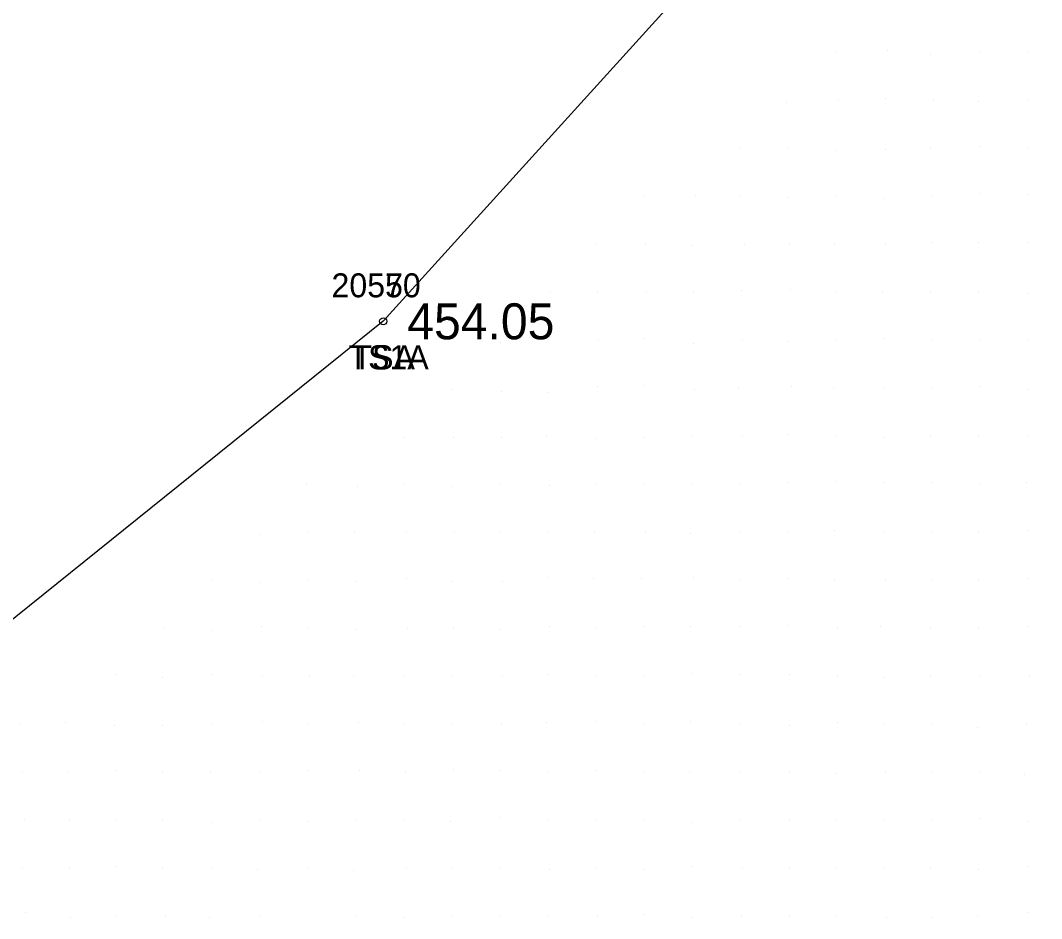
# Model space of a CAD drawing. Extents: x 1747760 to 1751131, y 649333 to 653784.
# Drawn here: x 1749057.32 to 1749099.9, y 651438.67 to 651476.11 of the extents above; entities that cross this region are included whole.
import ezdxf

# ---------------------------------------------------------------- set-up
doc = ezdxf.new("R2010")
doc.units = 0
for name, color, linetype in [('RD_DTM_BkLn2', 7, 'Continuous'), ('RD_DTM_BkLn_txCode', 7, 'Continuous'), ('RD_DTM_Spot', 7, 'Continuous'), ('RD_EX_TX_Misc_ELEV', 7, 'Continuous'), ('RD_SMD_Locator', 7, 'Continuous')]:
    doc.layers.add(name, color=color, linetype=linetype)

msp = doc.modelspace()

# ---------------------------------------------------------------- linework, layer by layer
at = {"layer": 'RD_DTM_BkLn2'}
for points in [[(1749072.449, 651463.568), (1749102.17, 651496.369), (1749126.542, 651516.467), (1749148.35, 651529.918), (1749165.728, 651545.441)], [(1749072.449, 651463.568), (1749050.274, 651445.743), (1749030.789, 651430.079), (1749011.304, 651414.416)]]:
    msp.add_lwpolyline(points, dxfattribs=at)
at = {"layer": 'RD_DTM_Spot'}
for p, q in [((1749091.356, 651474.816), (1749091.356, 651474.816)), ((1749093.471, 651474.844), (1749093.471, 651474.844)), ((1749095.285, 651474.697), (1749095.285, 651474.697)), ((1749097.31, 651474.81), (1749097.31, 651474.81)), ((1749099.306, 651474.798), (1749099.306, 651474.798)), ((1749089.246, 651472.694), (1749089.246, 651472.694)), ((1749091.422, 651472.754), (1749091.422, 651472.754)), ((1749093.385, 651472.838), (1749093.385, 651472.838)), ((1749095.394, 651472.826), (1749095.394, 651472.826)), ((1749097.271, 651472.74), (1749097.271, 651472.74)), ((1749099.296, 651472.808), (1749099.296, 651472.808)), ((1749097.327, 651470.844), (1749097.327, 651470.844)), ((1749087.317, 651470.817), (1749087.317, 651470.817)), ((1749089.328, 651470.774), (1749089.328, 651470.774)), ((1749091.316, 651470.685), (1749091.316, 651470.685)), ((1749093.381, 651470.748), (1749093.381, 651470.748)), ((1749095.272, 651470.792), (1749095.272, 651470.792)), ((1749099.348, 651470.815), (1749099.348, 651470.815)), ((1749083.356, 651468.808), (1749083.356, 651468.808)), ((1749085.457, 651468.82), (1749085.457, 651468.82)), ((1749087.33, 651468.754), (1749087.33, 651468.754)), ((1749089.32, 651468.748), (1749089.32, 651468.748)), ((1749091.358, 651468.767), (1749091.358, 651468.767)), ((1749095.31, 651468.759), (1749095.31, 651468.759)), ((1749097.314, 651468.878), (1749097.314, 651468.878)), ((1749099.353, 651468.846), (1749099.353, 651468.846)), ((1749093.359, 651468.703), (1749093.359, 651468.703)), ((1749081.338, 651466.831), (1749081.338, 651466.831)), ((1749083.403, 651466.767), (1749083.403, 651466.767)), ((1749085.323, 651466.734), (1749085.323, 651466.734)), ((1749087.501, 651466.763), (1749087.501, 651466.763)), ((1749089.398, 651466.778), (1749089.398, 651466.778)), ((1749091.256, 651466.805), (1749091.256, 651466.805)), ((1749093.377, 651466.807), (1749093.377, 651466.807)), ((1749095.361, 651466.859), (1749095.361, 651466.859)), ((1749097.257, 651466.842), (1749097.257, 651466.842)), ((1749099.345, 651466.844), (1749099.345, 651466.844)), ((1749079.435, 651464.773), (1749079.435, 651464.773)), ((1749081.385, 651464.777), (1749081.385, 651464.777)), ((1749083.433, 651464.761), (1749083.433, 651464.761)), ((1749085.365, 651464.802), (1749085.365, 651464.802)), ((1749087.372, 651464.852), (1749087.372, 651464.852)), ((1749089.446, 651464.88), (1749089.446, 651464.88)), ((1749091.318, 651464.767), (1749091.318, 651464.767)), ((1749093.281, 651464.792), (1749093.281, 651464.792)), ((1749095.259, 651464.798), (1749095.259, 651464.798)), ((1749097.251, 651464.757), (1749097.251, 651464.757)), ((1749099.347, 651464.709), (1749099.347, 651464.709)), ((1749079.27, 651462.837), (1749079.27, 651462.837)), ((1749081.415, 651462.772), (1749081.415, 651462.772)), ((1749083.291, 651462.84), (1749083.291, 651462.84)), ((1749087.445, 651462.788), (1749087.445, 651462.788)), ((1749091.333, 651462.823), (1749091.333, 651462.823)), ((1749093.363, 651462.859), (1749093.363, 651462.859)), ((1749095.299, 651462.799), (1749095.299, 651462.799)), ((1749097.317, 651462.802), (1749097.317, 651462.802)), ((1749099.299, 651462.785), (1749099.299, 651462.785)), ((1749077.337, 651462.686), (1749077.337, 651462.686)), ((1749085.378, 651462.662), (1749085.378, 651462.662)), ((1749089.307, 651462.731), (1749089.307, 651462.731)), ((1749075.355, 651460.723), (1749075.355, 651460.723)), ((1749077.396, 651460.657), (1749077.396, 651460.657)), ((1749081.373, 651460.838), (1749081.373, 651460.838)), ((1749083.29, 651460.88), (1749083.29, 651460.88)), ((1749085.439, 651460.746), (1749085.439, 651460.746)), ((1749087.272, 651460.75), (1749087.272, 651460.75)), ((1749089.455, 651460.86), (1749089.455, 651460.86)), ((1749091.241, 651460.767), (1749091.241, 651460.767)), ((1749093.346, 651460.755), (1749093.346, 651460.755)), ((1749095.288, 651460.794), (1749095.288, 651460.794)), ((1749097.317, 651460.864), (1749097.317, 651460.864)), ((1749099.349, 651460.717), (1749099.349, 651460.717)), ((1749079.353, 651460.612), (1749079.353, 651460.612)), ((1749073.348, 651458.718), (1749073.348, 651458.718)), ((1749075.378, 651458.74), (1749075.378, 651458.74)), ((1749077.377, 651458.738), (1749077.377, 651458.738)), ((1749079.268, 651458.756), (1749079.268, 651458.756)), ((1749081.335, 651458.699), (1749081.335, 651458.699)), ((1749083.282, 651458.726), (1749083.282, 651458.726)), ((1749085.337, 651458.759), (1749085.337, 651458.759)), ((1749087.424, 651458.805), (1749087.424, 651458.805)), ((1749089.334, 651458.859), (1749089.334, 651458.859)), ((1749091.336, 651458.758), (1749091.336, 651458.758)), ((1749093.336, 651458.73), (1749093.336, 651458.73)), ((1749095.285, 651458.819), (1749095.285, 651458.819)), ((1749097.25, 651458.772), (1749097.25, 651458.772)), ((1749099.306, 651458.758), (1749099.306, 651458.758)), ((1749073.345, 651456.796), (1749073.345, 651456.796)), ((1749085.315, 651456.825), (1749085.315, 651456.825)), ((1749089.297, 651456.849), (1749089.297, 651456.849)), ((1749091.357, 651456.904), (1749091.357, 651456.904)), ((1749093.3, 651456.851), (1749093.3, 651456.851)), ((1749095.347, 651456.837), (1749095.347, 651456.837)), ((1749099.258, 651456.844), (1749099.258, 651456.844)), ((1749069.263, 651456.787), (1749069.263, 651456.787)), ((1749071.364, 651456.694), (1749071.364, 651456.694)), ((1749075.301, 651456.684), (1749075.301, 651456.684)), ((1749077.356, 651456.761), (1749077.356, 651456.761)), ((1749079.38, 651456.734), (1749079.38, 651456.734)), ((1749081.293, 651456.767), (1749081.293, 651456.767)), ((1749083.281, 651456.77), (1749083.281, 651456.77)), ((1749087.359, 651456.756), (1749087.359, 651456.756)), ((1749097.297, 651456.758), (1749097.297, 651456.758)), ((1749067.311, 651454.686), (1749067.311, 651454.686)), ((1749069.33, 651454.773), (1749069.33, 651454.773)), ((1749071.245, 651454.796), (1749071.245, 651454.796)), ((1749073.42, 651454.758), (1749073.42, 651454.758)), ((1749075.406, 651454.805), (1749075.406, 651454.805)), ((1749077.322, 651454.751), (1749077.322, 651454.751)), ((1749079.339, 651454.775), (1749079.339, 651454.775)), ((1749081.277, 651454.789), (1749081.277, 651454.789)), ((1749083.366, 651454.818), (1749083.366, 651454.818)), ((1749085.265, 651454.72), (1749085.265, 651454.72)), ((1749087.32, 651454.749), (1749087.32, 651454.749)), ((1749089.358, 651454.783), (1749089.358, 651454.783)), ((1749091.247, 651454.841), (1749091.247, 651454.841)), ((1749093.338, 651454.824), (1749093.338, 651454.824)), ((1749095.365, 651454.823), (1749095.365, 651454.823)), ((1749097.286, 651454.811), (1749097.286, 651454.811)), ((1749099.296, 651454.834), (1749099.296, 651454.834)), ((1749065.304, 651452.79), (1749065.304, 651452.79)), ((1749067.345, 651452.697), (1749067.345, 651452.697)), ((1749069.271, 651452.745), (1749069.271, 651452.745)), ((1749071.345, 651452.714), (1749071.345, 651452.714)), ((1749073.411, 651452.847), (1749073.411, 651452.847)), ((1749075.322, 651452.703), (1749075.322, 651452.703)), ((1749077.406, 651452.73), (1749077.406, 651452.73)), ((1749079.326, 651452.874), (1749079.326, 651452.874)), ((1749081.228, 651452.837), (1749081.228, 651452.837)), ((1749083.204, 651452.864), (1749083.204, 651452.864)), ((1749085.379, 651452.905), (1749085.379, 651452.905)), ((1749087.317, 651452.806), (1749087.317, 651452.806)), ((1749089.342, 651452.832), (1749089.342, 651452.832)), ((1749091.273, 651452.783), (1749091.273, 651452.783)), ((1749093.373, 651452.78), (1749093.373, 651452.78)), ((1749095.308, 651452.779), (1749095.308, 651452.779)), ((1749097.272, 651452.775), (1749097.272, 651452.775)), ((1749099.332, 651452.825), (1749099.332, 651452.825)), ((1749079.378, 651450.854), (1749079.378, 651450.854)), ((1749083.307, 651450.836), (1749083.307, 651450.836)), ((1749085.272, 651450.837), (1749085.272, 651450.837)), ((1749087.285, 651450.86), (1749087.285, 651450.86)), ((1749089.361, 651450.866), (1749089.361, 651450.866)), ((1749093.186, 651450.834), (1749093.186, 651450.834)), ((1749099.355, 651450.859), (1749099.355, 651450.859)), ((1749063.333, 651450.81), (1749063.333, 651450.81)), ((1749065.317, 651450.688), (1749065.317, 651450.688)), ((1749067.371, 651450.825), (1749067.371, 651450.825)), ((1749069.274, 651450.768), (1749069.274, 651450.768)), ((1749071.321, 651450.715), (1749071.321, 651450.715)), ((1749073.467, 651450.78), (1749073.467, 651450.78)), ((1749075.388, 651450.795), (1749075.388, 651450.795)), ((1749077.333, 651450.729), (1749077.333, 651450.729)), ((1749081.302, 651450.769), (1749081.302, 651450.769)), ((1749091.369, 651450.802), (1749091.369, 651450.802)), ((1749095.259, 651450.777), (1749095.259, 651450.777)), ((1749097.263, 651450.802), (1749097.263, 651450.802)), ((1749061.271, 651448.828), (1749061.271, 651448.828)), ((1749063.229, 651448.731), (1749063.229, 651448.731)), ((1749065.35, 651448.847), (1749065.35, 651448.847)), ((1749067.394, 651448.755), (1749067.394, 651448.755)), ((1749069.366, 651448.804), (1749069.366, 651448.804)), ((1749071.216, 651448.776), (1749071.216, 651448.776)), ((1749073.276, 651448.782), (1749073.276, 651448.782)), ((1749075.32, 651448.814), (1749075.32, 651448.814)), ((1749077.404, 651448.813), (1749077.404, 651448.813)), ((1749079.305, 651448.84), (1749079.305, 651448.84)), ((1749081.312, 651448.812), (1749081.312, 651448.812)), ((1749083.318, 651448.785), (1749083.318, 651448.785)), ((1749085.291, 651448.872), (1749085.291, 651448.872)), ((1749087.322, 651448.844), (1749087.322, 651448.844)), ((1749089.396, 651448.852), (1749089.396, 651448.852)), ((1749091.379, 651448.801), (1749091.379, 651448.801)), ((1749093.362, 651448.712), (1749093.362, 651448.712)), ((1749095.254, 651448.791), (1749095.254, 651448.791)), ((1749097.331, 651448.786), (1749097.331, 651448.786)), ((1749099.391, 651448.757), (1749099.391, 651448.757)), ((1749057.33, 651446.811), (1749057.33, 651446.811)), ((1749059.204, 651446.835), (1749059.204, 651446.835)), ((1749061.233, 651446.723), (1749061.233, 651446.723)), ((1749063.233, 651446.71), (1749063.233, 651446.71)), ((1749065.294, 651446.744), (1749065.294, 651446.744)), ((1749067.401, 651446.865), (1749067.401, 651446.865)), ((1749069.315, 651446.771), (1749069.315, 651446.771)), ((1749071.423, 651446.829), (1749071.423, 651446.829)), ((1749073.303, 651446.813), (1749073.303, 651446.813)), ((1749075.35, 651446.772), (1749075.35, 651446.772)), ((1749077.381, 651446.787), (1749077.381, 651446.787)), ((1749079.275, 651446.862), (1749079.275, 651446.862)), ((1749081.345, 651446.888), (1749081.345, 651446.888)), ((1749083.283, 651446.799), (1749083.283, 651446.799)), ((1749085.253, 651446.865), (1749085.253, 651446.865)), ((1749087.314, 651446.81), (1749087.314, 651446.81)), ((1749089.375, 651446.726), (1749089.375, 651446.726)), ((1749091.393, 651446.831), (1749091.393, 651446.831)), ((1749093.365, 651446.808), (1749093.365, 651446.808)), ((1749095.369, 651446.744), (1749095.369, 651446.744)), ((1749097.231, 651446.639), (1749097.231, 651446.639)), ((1749099.284, 651446.765), (1749099.284, 651446.765)), ((1749057.396, 651444.78), (1749057.396, 651444.78)), ((1749059.282, 651444.78), (1749059.282, 651444.78)), ((1749061.32, 651444.837), (1749061.32, 651444.837)), ((1749063.254, 651444.738), (1749063.254, 651444.738)), ((1749065.262, 651444.752), (1749065.262, 651444.752)), ((1749067.28, 651444.793), (1749067.28, 651444.793)), ((1749069.345, 651444.85), (1749069.345, 651444.85)), ((1749071.46, 651444.825), (1749071.46, 651444.825)), ((1749073.37, 651444.785), (1749073.37, 651444.785)), ((1749075.377, 651444.863), (1749075.377, 651444.863)), ((1749077.301, 651444.821), (1749077.301, 651444.821)), ((1749079.316, 651444.798), (1749079.316, 651444.798)), ((1749081.294, 651444.836), (1749081.294, 651444.836)), ((1749083.358, 651444.795), (1749083.358, 651444.795)), ((1749085.226, 651444.773), (1749085.226, 651444.773)), ((1749087.313, 651444.747), (1749087.313, 651444.747)), ((1749089.393, 651444.797), (1749089.393, 651444.797)), ((1749091.345, 651444.728), (1749091.345, 651444.728)), ((1749093.378, 651444.762), (1749093.378, 651444.762)), ((1749095.337, 651444.813), (1749095.337, 651444.813)), ((1749097.288, 651444.752), (1749097.288, 651444.752)), ((1749099.205, 651444.68), (1749099.205, 651444.68)), ((1749057.495, 651442.797), (1749057.495, 651442.797)), ((1749059.364, 651442.791), (1749059.364, 651442.791)), ((1749063.224, 651442.746), (1749063.224, 651442.746)), ((1749067.32, 651442.756), (1749067.32, 651442.756)), ((1749071.273, 651442.799), (1749071.273, 651442.799)), ((1749073.352, 651442.768), (1749073.352, 651442.768)), ((1749077.327, 651442.879), (1749077.327, 651442.879)), ((1749081.347, 651442.811), (1749081.347, 651442.811)), ((1749083.341, 651442.786), (1749083.341, 651442.786)), ((1749089.374, 651442.753), (1749089.374, 651442.753)), ((1749091.323, 651442.746), (1749091.323, 651442.746)), ((1749095.359, 651442.771), (1749095.359, 651442.771)), ((1749097.31, 651442.847), (1749097.31, 651442.847)), ((1749061.329, 651442.736), (1749061.329, 651442.736)), ((1749065.288, 651442.681), (1749065.288, 651442.681)), ((1749069.304, 651442.714), (1749069.304, 651442.714)), ((1749075.254, 651442.718), (1749075.254, 651442.718)), ((1749079.286, 651442.741), (1749079.286, 651442.741)), ((1749085.356, 651442.693), (1749085.356, 651442.693)), ((1749087.315, 651442.74), (1749087.315, 651442.74)), ((1749093.298, 651442.738), (1749093.298, 651442.738)), ((1749099.308, 651442.711), (1749099.308, 651442.711)), ((1749057.4, 651440.756), (1749057.4, 651440.756)), ((1749059.365, 651440.738), (1749059.365, 651440.738)), ((1749061.296, 651440.82), (1749061.296, 651440.82)), ((1749063.252, 651440.752), (1749063.252, 651440.752)), ((1749065.279, 651440.779), (1749065.279, 651440.779)), ((1749067.224, 651440.704), (1749067.224, 651440.704)), ((1749069.345, 651440.77), (1749069.345, 651440.77)), ((1749071.225, 651440.692), (1749071.225, 651440.692)), ((1749073.425, 651440.764), (1749073.425, 651440.764)), ((1749075.344, 651440.787), (1749075.344, 651440.787)), ((1749077.323, 651440.748), (1749077.323, 651440.748)), ((1749079.385, 651440.725), (1749079.385, 651440.725)), ((1749081.326, 651440.748), (1749081.326, 651440.748)), ((1749083.324, 651440.729), (1749083.324, 651440.729)), ((1749085.282, 651440.821), (1749085.282, 651440.821)), ((1749087.427, 651440.754), (1749087.427, 651440.754)), ((1749089.402, 651440.777), (1749089.402, 651440.777)), ((1749091.327, 651440.79), (1749091.327, 651440.79)), ((1749093.343, 651440.816), (1749093.343, 651440.816)), ((1749095.274, 651440.8), (1749095.274, 651440.8)), ((1749097.255, 651440.695), (1749097.255, 651440.695)), ((1749099.326, 651440.837), (1749099.326, 651440.837)), ((1749099.366, 651438.921), (1749099.366, 651438.921)), ((1749057.551, 651438.9), (1749057.551, 651438.9)), ((1749059.421, 651438.727), (1749059.421, 651438.727)), ((1749061.299, 651438.774), (1749061.299, 651438.774)), ((1749063.387, 651438.793), (1749063.387, 651438.793)), ((1749065.225, 651438.717), (1749065.225, 651438.717)), ((1749067.272, 651438.796), (1749067.272, 651438.796)), ((1749071.341, 651438.768), (1749071.341, 651438.768)), ((1749073.288, 651438.713), (1749073.288, 651438.713)), ((1749075.288, 651438.745), (1749075.288, 651438.745)), ((1749077.346, 651438.77), (1749077.346, 651438.77)), ((1749079.337, 651438.805), (1749079.337, 651438.805)), ((1749081.388, 651438.787), (1749081.388, 651438.787)), ((1749083.357, 651438.838), (1749083.357, 651438.838)), ((1749085.289, 651438.694), (1749085.289, 651438.694)), ((1749087.375, 651438.762), (1749087.375, 651438.762)), ((1749089.405, 651438.761), (1749089.405, 651438.761)), ((1749091.339, 651438.775), (1749091.339, 651438.775)), ((1749093.415, 651438.711), (1749093.415, 651438.711)), ((1749095.328, 651438.711), (1749095.328, 651438.711)), ((1749097.224, 651438.796), (1749097.224, 651438.796))]:
    msp.add_line(p, q, dxfattribs=at)
at = {"layer": 'RD_SMD_Locator'}
msp.add_circle((1749072.449, 651463.568), 0.15, dxfattribs=at)
msp.add_circle((1749072.449, 651463.568), 0.15, dxfattribs=at)

# ---------------------------------------------------------------- texts
at = {"layer": 'RD_DTM_BkLn_txCode'}
for s, p in [('20550', (1749070.292, 651464.568)), ('20570', (1749070.292, 651464.568)), ('TS1A', (1749071, 651461.568)), ('TSA', (1749071.166, 651461.568))]:
    msp.add_text(s, height=1, dxfattribs=at).set_placement(p)
at = {"layer": 'RD_EX_TX_Misc_ELEV'}
msp.add_text('454.05', height=1.5, dxfattribs=at).set_placement((1749073.449, 651462.818))
msp.add_text('454.05', height=1.5, dxfattribs=at).set_placement((1749073.449, 651462.818))

doc.saveas('drawing.dxf')
